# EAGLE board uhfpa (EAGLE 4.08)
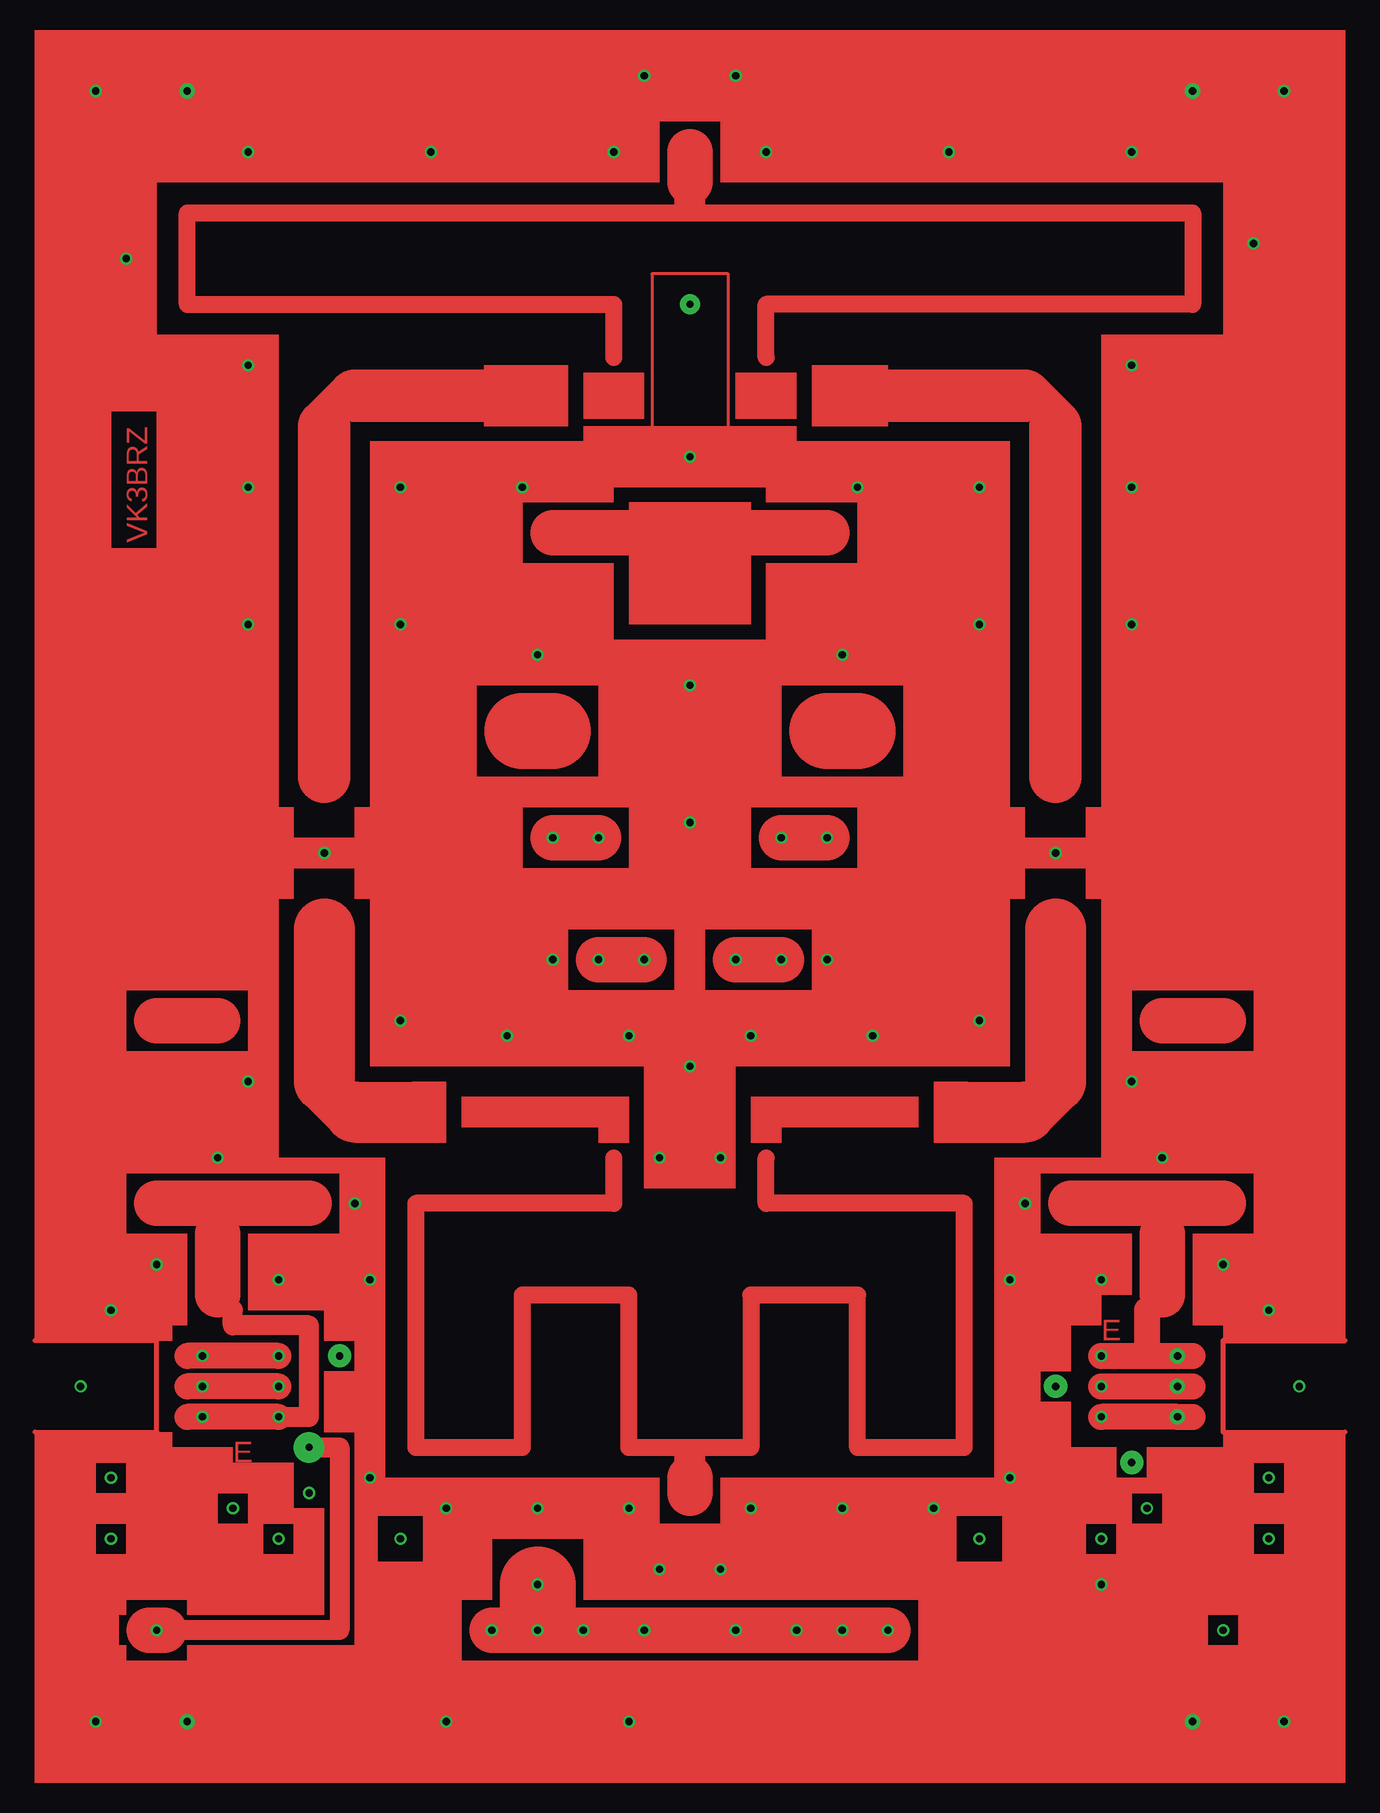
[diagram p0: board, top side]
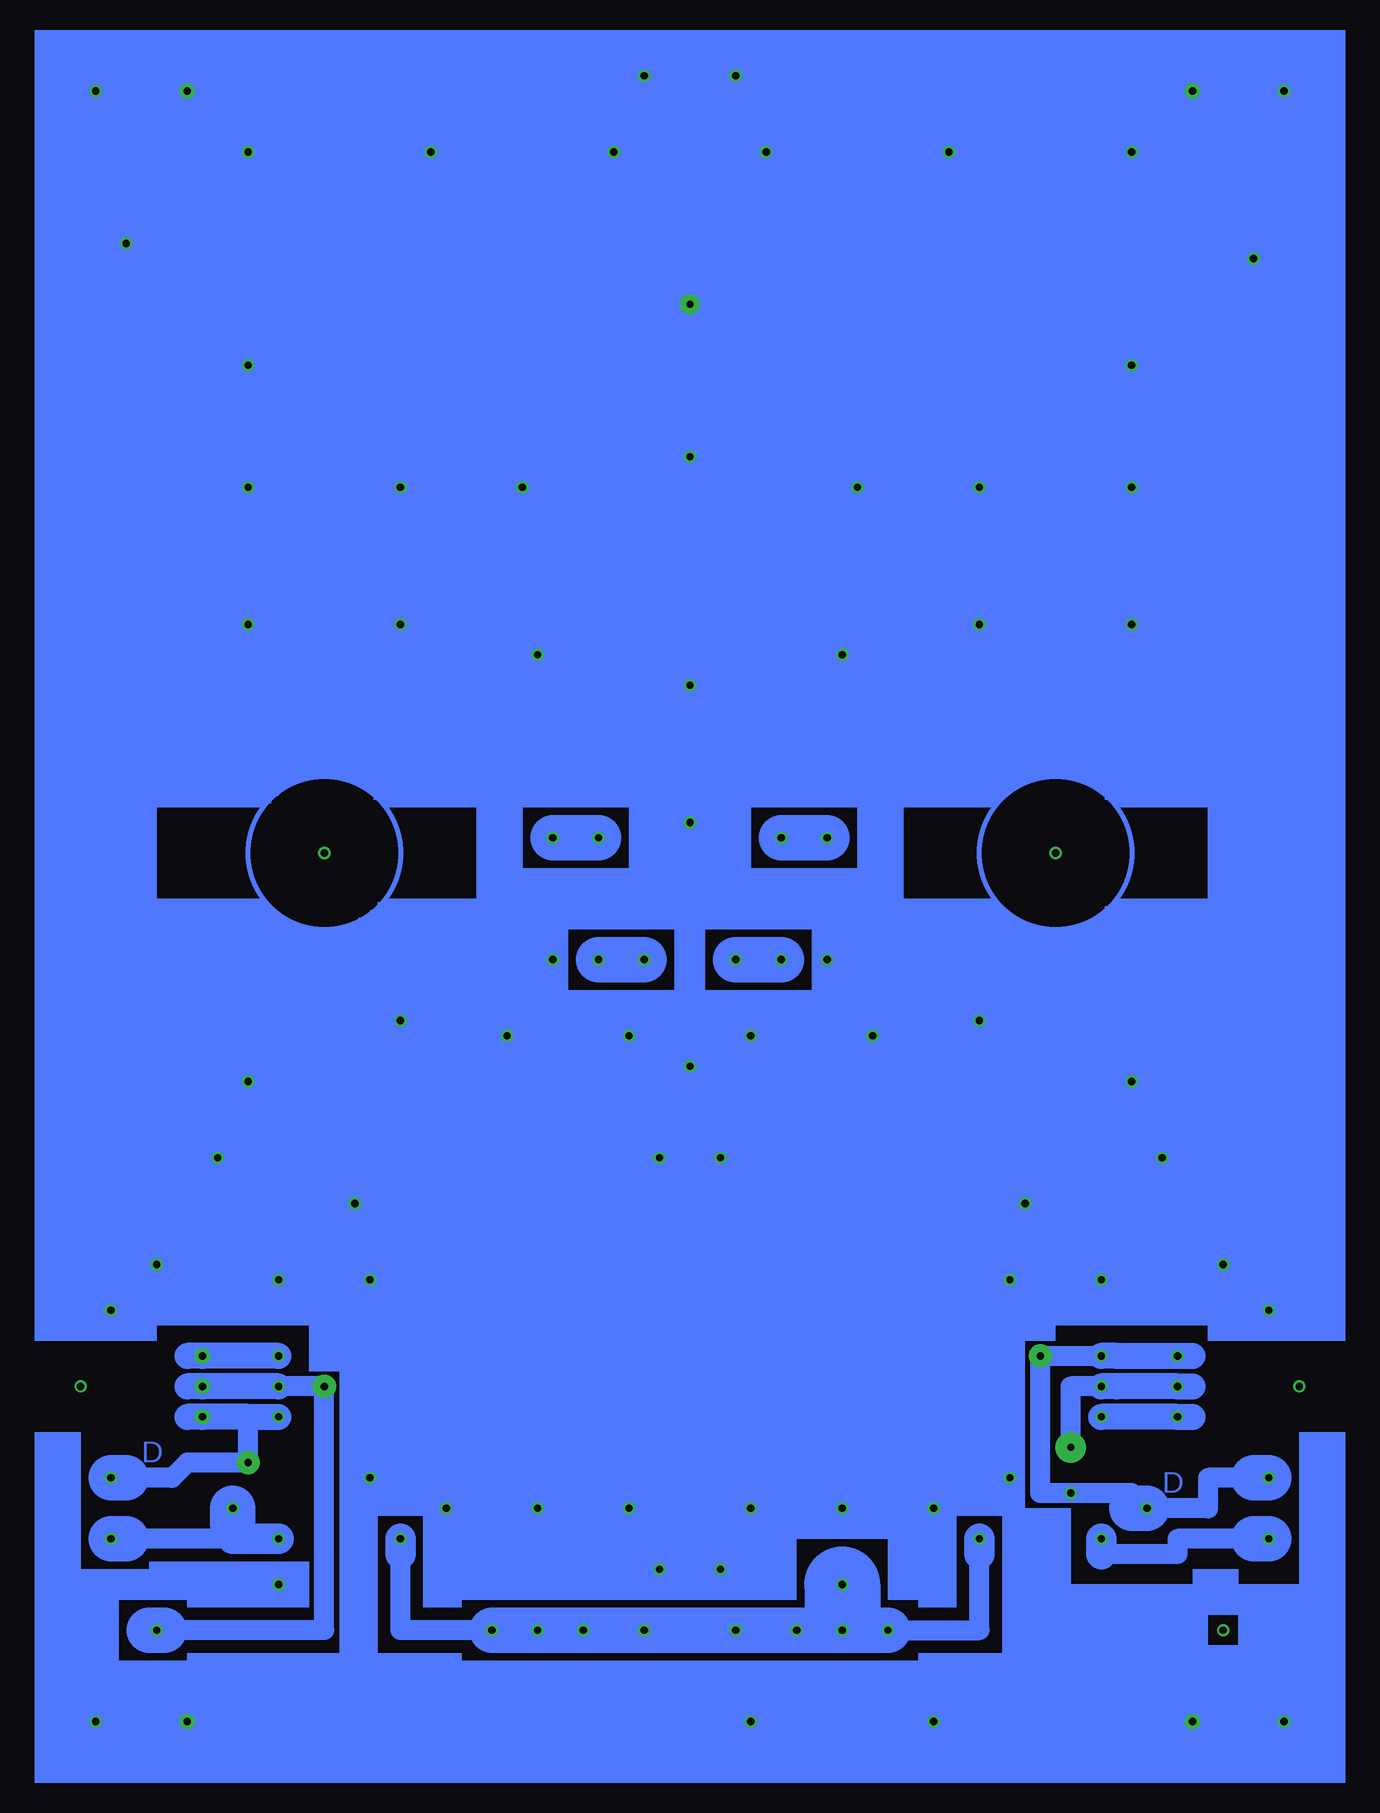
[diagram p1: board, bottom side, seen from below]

No outline drawn. Coordinates in mm, seen from the top.
Copper layers used: Top, Bottom

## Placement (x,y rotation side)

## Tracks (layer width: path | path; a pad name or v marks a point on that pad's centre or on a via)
S$1  (via drill 0.61 pad 1.68)
  other vias: 50.8,97.79
S$2  (via drill 0.61 pad 0.81)
  other vias: 20.32,52.07
S$3  (via drill 0.61 pad 0.81)
  other vias: 81.28,52.07
S$4
  Top 1.422: 45.72,2.54 45.72,15.24
S$7
  Top 1.422: 36.83,15.24 45.72,15.24
S$8
  Top 1.422: 19.05,31.75 21.59,29.21
S$9
  Top 3.81: 11.43,38.1 6.35,38.1
S$10
  Top 4.394: 20.32,58.42 20.32,87.63
S$11
  Top 5.08: 73.66,30.48 78.74,30.48
S$12
  Top 0.254: 53.98,86.36 53.98,100.33 47.62,100.33 47.62,86.36
S$13
  Top 4.394: 81.28,58.42 81.28,87.63
S$14
  Top 1.422: 44.45,26.67 44.45,22.86 27.94,22.86 27.94,2.54 36.83,2.54
S$15
  Top 1.422: 64.77,2.54 73.66,2.54 73.66,22.86 57.15,22.86 57.15,26.67
S$16  (via drill 0.61 pad 1.02)
  other vias: 50.8,85.09
S$17
  Top 5.08: 20.32,45.72 20.32,33.02
S$18
  Top 5.08: 22.86,30.48 27.94,30.48
S$19
  Top 5.08: 81.28,45.72 81.28,33.02
S$20
  Top 4.394: 22.86,90.17 36.83,90.17
S$21
  Top 0.813: 21.59,91.44 19.05,88.9
S$22  (via drill 0.61)
  other vias: 26.67,82.55
S$23
  Top 4.394: 63.5,90.17 78.74,90.17
S$24
  Top 0.813: 80.01,91.44 82.55,88.9
S$25
  Top 3.81: 46.99,78.74 39.37,78.74
S$26  (via drill 0.61)
  other vias: 36.83,82.55
S$27
  Top 1.422: 80.01,29.21 82.55,31.75
S$28  (via drill 0.61)
  other vias: 74.93,82.55
S$29  (via drill 0.61)
  other vias: 64.77,82.55
S$30  (via drill 0.61)
  other vias: 26.67,71.12
S$31
  Top 1.422: 36.83,2.54 36.83,15.24
S$32  (via drill 0.61 pad 1.02)
  other vias: 13.97,71.12
S$33  (via drill 0.61)
  other vias: 74.93,71.12
S$34  (via drill 0.61)
  other vias: 87.63,71.12
S$35
  Top 1.422: 64.77,15.24 55.88,15.24 55.88,2.54
S$36
  Top 1.422: 57.15,93.34 57.15,97.79 92.71,97.79 92.71,105.41 8.89,105.41 8.89,97.79 44.45,97.79 44.45,93.34
S$37  (via drill 0.61 pad 1.02)
  other vias: 3.81,101.6
S$38  (via drill 0.61 pad 1.02)
  other vias: 97.79,102.87
S$39  (via drill 0.61 pad 1.02)
  other vias: 44.45,110.49
S$40  (via drill 0.61)
  other vias: 13.97,92.71
S$41  (via drill 0.61)
  other vias: 87.63,92.71
S$42  (via drill 0.61)
  other vias: 26.67,38.1
S$43
  Top 3.81: 54.61,78.74 62.23,78.74
S$44  (via drill 0.61)
  other vias: 74.93,38.1
S$45
  Top 3.81: 90.17,38.1 95.25,38.1
S$46
  Top 6.35: 39.37,62.23 36.83,62.23
S$47
  Top 0.406: -3.81,3.81 6.35,3.81 6.35,11.43 -3.81,11.43
S$48
  Top 1.422: 45.72,2.54 55.88,2.54
S$49
  Top 6.35: 64.77,62.23 62.23,62.23
S$50  (via drill 0.61)
  Top 3.81: v43.18,53.34 v39.37,53.34
  Bottom 3.81: v39.37,53.34 v43.18,53.34
S$51  (via drill 0.61 pad 1.02)
  other vias: 53.34,26.67
S$52  (via drill 0.61)
  Top 3.81: v58.42,53.34 v62.23,53.34
  Bottom 3.81: v58.42,53.34 v62.23,53.34
S$53  (via drill 0.61 pad 1.02)
  Top 3.81: 43.18,43.18 v46.99,43.18
  Bottom 3.81: v46.99,43.18 43.18,43.18
S$56  (via drill 0.61 pad 1.02)
  other vias: 39.37,43.18
S$57  (via drill 0.61 pad 1.02)
  other vias: 58.42,43.18
S$58  (via drill 0.61 pad 1.02)
  other vias: 43.18,43.18
S$59
  Top 3.81: 6.35,22.86 19.05,22.86
S$60
  Top 1.422: 64.77,2.54 64.77,15.24
S$61  (via drill 0.61 pad 1.02)
  other vias: 16.51,16.51
S$62  (via drill 0.61 pad 1.02)
  other vias: 57.15,110.49
S$63  (via drill 0.61 pad 1.02)
  other vias: 46.99,116.84
S$64  (via drill 0.61 pad 1.02)
  other vias: 54.61,116.84
S$65  (via drill 0.61 pad 1.02)
  other vias: 13.97,110.49
S$66  (via drill 0.61 pad 1.02)
  other vias: 13.97,82.55
S$67  (via drill 0.61 pad 1.02)
  other vias: 29.21,110.49
S$68  (via drill 0.61 pad 1.02)
  other vias: 87.63,110.49
S$69  (via drill 0.61 pad 1.02)
  other vias: 72.39,110.49
S$70  (via drill 0.61 pad 1.02)
  Bottom 3.81: v2.54,-5.08 3.81,-5.08
S$71  (via drill 0.61 pad 1.02)
  Top 1.676: 12.7,13.97 12.7,12.7 19.05,12.7 19.05,5.08 v16.51,5.08 v10.16,5.08
  Top 2.184: v16.51,5.08 8.89,5.08
  Bottom 2.184: 8.89,5.08 v10.16,5.08 v16.51,5.08
S$72  (via drill 0.61 pad 1.02, 0.61 pad 2.54)
  Top 1.676: v19.05,2.54 21.59,2.54 21.59,-12.7 6.99,-12.7
  Top 2.184: v16.51,7.62 8.89,7.62
  Top 3.81: 5.71,-12.7 v6.35,-12.7 6.99,-12.7
  Bottom 1.676: v19.05,2.54 19.05,7.62 15.24,7.62
  Bottom 2.184: 8.89,7.62 v10.16,7.62 15.24,7.62 v16.51,7.62
S$73
  Top 3.81: 82.55,22.86 95.25,22.86
S$74  (via drill 0.61 pad 1.02)
  Bottom 1.676: 5.08,-5.08 10.16,-5.08 10.16,-6.35 16.51,-6.35
  Bottom 2.54: v16.51,-5.08 16.51,-6.35
S$75  (via drill 0.61 pad 1.02)
  Top 3.81: v34.29,-12.7 v46.99,-12.7 v54.61,-12.7 67.31,-12.7
  Bottom 1.676: v34.29,-12.7 26.67,-12.7 26.67,-6.35
  Bottom 2.54: v26.67,-5.08 26.67,-6.35
  Bottom 3.81: v34.29,-12.7 v38.1,-12.7 v41.91,-12.7 v46.99,-12.7 v54.61,-12.7 v59.69,-12.7 v63.5,-12.7 67.31,-12.7
S$76  (via drill 0.61 pad 1.02)
  other vias: 45.72,-2.54
S$77  (via drill 0.61 pad 1.02)
  Bottom 3.81: v88.9,-2.54 88.9,-3.81
S$78
  Top 0.406: 105.41,11.43 95.25,11.43 95.25,3.81 105.41,3.81
S$79  (via drill 0.61 pad 1.02, 0.61 pad 1.27)
  Top 2.184: v85.09,7.62 v91.44,7.62 92.71,7.62
  Bottom 2.184: v85.09,7.62 v91.44,7.62 92.71,7.62
S$80
  Bottom 1.676: 97.79,0 93.98,0 92.71,1.27 87.63,1.27
  Bottom 3.81: 97.79,0 99.06,0
S$81  (via drill 0.61 pad 1.02)
  other vias: 99.06,0
S$82  (via drill 0.61 pad 1.02)
  Bottom 1.676: v67.31,-12.7 74.93,-12.7 74.93,-6.35
  Bottom 2.54: 74.93,-6.35 v74.93,-5.08
S$83  (via drill 0.61 pad 1.02)
  other vias: 85.09,5.08
S$84  (via drill 0.61 pad 1.02)
  other vias: 87.63,82.55
S$85  (via drill 0.61 pad 1.27)
  Top 2.184: 92.71,5.08 v91.44,5.08 85.09,5.08
  Bottom 1.676: 87.63,1.27 87.63,5.08
  Bottom 2.184: 85.09,5.08 87.63,5.08 v91.44,5.08 92.71,5.08
S$86  (via drill 0.61 pad 1.02)
  other vias: 85.09,10.16
S$87  (via drill 0.61 pad 1.02, 0.61 pad 1.93)
  Bottom 1.676: 86.36,7.62 v81.28,7.62 81.28,-12.7 94.61,-12.7
  Bottom 3.81: 94.61,-12.7 v95.25,-12.7 95.89,-12.7
S$88  (via drill 0.61 pad 1.02, 0.61 pad 1.93)
  Top 2.184: v16.51,10.16 8.89,10.16
  Bottom 1.676: 15.24,10.16 v21.59,10.16 21.59,-1.27 v19.05,-1.27 13.97,-1.27
  Bottom 2.184: 8.89,10.16 v10.16,10.16 15.24,10.16 v16.51,10.16
S$89  (via drill 0.61 pad 1.27)
  Top 2.184: 85.09,10.16 88.9,10.16 | 88.9,10.16 v91.44,10.16 92.71,10.16 | 88.9,13.97 88.9,10.16
  Bottom 2.184: 85.09,10.16 v91.44,10.16 92.71,10.16
S$90
  Top 3.81: 50.8,0 50.8,-1.27
S$91  (via drill 0.61 pad 1.02)
  Bottom 1.676: 88.9,-5.08 97.79,-5.08
  Bottom 2.54: 88.9,-5.08 v85.09,-5.08
  Bottom 3.81: 97.79,-5.08 v99.06,-5.08
S$92  (via drill 0.61 pad 1.02)
  other vias: 48.26,26.67
S$93  (via drill 0.61 pad 1.02)
  Bottom 1.676: v12.7,-2.54 7.62,-2.54 7.62,0 3.81,0
  Bottom 3.81: v2.54,0 3.81,0 | v12.7,-2.54 13.97,-2.54
S$94  (via drill 0.61 pad 1.27)
  other vias: 8.89,115.57
S$95
  Top 3.81: 90.17,20.32 90.17,15.24
S$96  (via drill 0.61 pad 1.27)
  other vias: 92.71,115.57
S$97
  Top 3.81: 11.43,15.24 11.43,20.32
S$98  (via drill 0.61 pad 1.02)
  other vias: 55.88,-2.54
S$99
  Top 3.81: 50.8,110.49 50.8,107.95
S$100  (via drill 0.61 pad 1.27)
  other vias: 8.89,-20.32
S$101  (via drill 0.61 pad 1.02)
  other vias: 48.26,-7.62
S$102  (via drill 0.61 pad 1.02)
  other vias: 53.34,-7.62
S$103  (via drill 0.61 pad 1.02)
  other vias: 38.1,-2.54
S$104  (via drill 0.61 pad 1.02)
  other vias: 63.5,-2.54
S$105  (via drill 0.61 pad 1.02)
  other vias: 99.06,13.97
S$106  (via drill 0.61 pad 1.02)
  other vias: 95.25,17.78
S$107  (via drill 0.61 pad 1.02)
  other vias: 2.54,13.97
S$108  (via drill 0.61 pad 1.02)
  other vias: 6.35,17.78
S$109  (via drill 0.61 pad 1.02)
  Top 6.35: v38.1,-8.89 38.1,-11.43
  Bottom 6.35: v38.1,-8.89 38.1,-11.43
S$110  (via drill 0.61 pad 1.02)
  other vias: 13.97,33.02
S$111  (via drill 0.61 pad 1.02)
  other vias: 87.63,33.02
S$112  (via drill 0.61 pad 1.02)
  other vias: 85.09,16.51
S$113  (via drill 0.61 pad 1.02)
  other vias: 78.74,22.86
S$114  (via drill 0.61 pad 1.02)
  other vias: 90.17,26.67
S$115  (via drill 0.61 pad 1.02)
  other vias: 11.43,26.67
S$116  (via drill 0.61 pad 1.02)
  other vias: 71.12,-2.54
S$117  (via drill 0.61 pad 1.02)
  other vias: 30.48,-2.54
S$118  (via drill 0.61 pad 1.93)
  other vias: 87.63,1.27
S$119  (via drill 0.61 pad 1.02)
  other vias: 77.47,16.51
S$120  (via drill 0.61 pad 1.02)
  other vias: 77.47,0
S$121  (via drill 0.61 pad 1.02)
  other vias: 24.13,0
S$122  (via drill 0.61 pad 1.02)
  other vias: 35.56,36.83
S$123  (via drill 0.61 pad 1.02)
  other vias: 66.04,36.83
S$124  (via drill 0.61 pad 1.02)
  other vias: 55.88,36.83
S$125  (via drill 0.61 pad 1.02)
  other vias: 45.72,36.83
S$126  (via drill 0.61 pad 1.02)
  other vias: 50.8,34.29
S$127  (via drill 0.61 pad 1.02)
  other vias: 22.86,22.86
S$128  (via drill 0.61 pad 1.27)
  other vias: 92.71,-20.32
S$129  (via drill 0.61 pad 1.02)
  other vias: 50.8,66.04
S$130  (via drill 0.61 pad 1.02)
  other vias: 50.8,54.61
S$131  (via drill 0.61 pad 1.02)
  other vias: 38.1,68.58
S$132  (via drill 0.61 pad 1.02)
  other vias: 63.5,68.58
S$133  (via drill 0.61 pad 1.02)
  other vias: 85.09,-8.89
S$134  (via drill 0.61 pad 1.02)
  other vias: 30.48,-20.32
S$135  (via drill 0.61 pad 1.02)
  other vias: 45.72,-20.32
S$136  (via drill 0.61 pad 1.02)
  Top 3.81: v54.61,43.18 58.42,43.18
  Bottom 3.81: v54.61,43.18 58.42,43.18
S$137  (via drill 0.61 pad 1.02)
  other vias: 62.23,43.18
S$138  (via drill 0.61 pad 1.02)
  other vias: 0,7.62
S$139  (via drill 0.61 pad 1.02)
  other vias: 101.6,7.62
S$140  (via drill 0.61 pad 1.02)
  other vias: 1.27,-20.32
S$141  (via drill 0.61 pad 1.02)
  other vias: 100.33,-20.32
S$142  (via drill 0.61 pad 1.02)
  other vias: 100.33,115.57
S$143  (via drill 0.61 pad 1.02)
  other vias: 1.27,115.57
S$144  (via drill 0.61 pad 1.02)
  other vias: 24.13,16.51
(copper drawn outside any net)
  shapes: Bottom area x163, Bottom circle x2, Top area x251

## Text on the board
Top: VK3BRZ | E | E
Bottom: D | D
